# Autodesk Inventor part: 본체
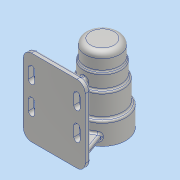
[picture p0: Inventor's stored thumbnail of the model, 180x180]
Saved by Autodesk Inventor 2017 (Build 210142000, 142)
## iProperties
Part Number: 본체
Material: 알루미늄 6061
Document SubType Name: Modeling
Designer: MRC
Density: 2.7 g/cm^3
Appearance: 알루미늄 - 평지
Mass: 691.206 g
Surface Area: 698.864 cm^2
Volume: 256.002 cm^3
Author: MRC
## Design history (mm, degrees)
sketch "스케치1"
  geometry: L1 (0, -56)-(34, -56); L2 (34, -56)-(34, -24); L3 (34, -24)-(30, -24); L4 (30, -24)-(30, 10); L5 (30, 10)-(27, 10); L6 (27, 10)-(27, 32); L7 (27, 32)-(25, 32); L8 (25, 32)-(25, 56); L9 (25, 56)-(0, 56); L10 (0, -56)-(0, 56); L11 (21, -56)-(21, -41); L12 (21, -41)-(24, -41); L13 (24, -41)-(24, 13); L14 (24, 13)-(21, 13); L15 (21, 13)-(21, 25); L16 (21, 25)-(17.5, 25); L17 (17.5, 25)-(17.5, 43); L18 (17.5, 43)-(16, 43); L19 (16, 43)-(16, 47); L20 (16, 47)-(10.5, 47); L21 (10.5, 47)-(10.5, 50); L22 (10.5, 50)-(0, 50); L23 (-62, 56)-(-70, 56); L24 (-70, 56)-(-70, -56); L25 (-70, -56)-(-62, -56); L26 (-62, -56)-(-62, 56); 4 further points
  constraints: 52 end point, 13 perpendicular, 8 horizontal, 3 midpoint, 3 parallel, 2 horizontal alignment, 2 point on line, 2 vertical, 1 coincident, 1 vertical alignment
  dimensions: "d0" = 112 distance between parallel lines of L1 L9; "d5" = 24 distance from line of L6.end L9; "d6" = 46 distance between parallel lines of L5 L9; "d7" = 80 distance between parallel lines of L3 L9; "d8" = 68 diameter of L2 L10; "d9" = 60 diameter of L4 L10; "d10" = 54 diameter of L6 L10; "d11" = 50 diameter of L8 L10; "d12" = 42 diameter of L11 L10; "d13" = 15 distance of L11.start L11.end; "d14" = 48 diameter of L13 L10; "d15" = 54 distance of L12.end L13.end; "d16" = 12 distance of L14.end L15.end; "d17" = 18 distance of L16.end L17.end; "d18" = 35 diameter of L17 L10; "d19" = 32 diameter of L19 L10; "d20" = 21 diameter of L21 L10; "d21" = 4 distance between parallel lines of L18 L20; "d22" = 3 distance between parallel lines of L20 L22; "d23" = 70 distance between parallel lines of L24 L10; "d24" = 8 distance of L24.end L25.end
revolve "회전1" stored, may be unused: angle "d25" = 90 deg
extrude "돌출1" join sketch "스케치1" stored distance "d26" = 90; taper "d27" = 0 deg
sketch "스케치2"
  geometry: L1 (-25, 56)-(25, 56) reference; L2 (25, 56)-(25, 32) reference; L3 (25, 32)-(27, 32) reference; L4 (27, 32)-(27, 10) reference; L5 (27, 10)-(30, 10) reference; L6 (30, 10)-(30, -24) reference; L7 (30, -24)-(34, -24) reference; L8 (34, -24)-(34, -56) reference; L9 (34, -56)-(21, -56) reference; L10 (21, -56)-(21, -41) reference; L11 (21, -41)-(24, -41) reference; L12 (24, -41)-(24, 13) reference; L13 (24, 13)-(21, 13) reference; L14 (21, 13)-(21, 25) reference; L15 (21, 25)-(17.5, 25) reference; L16 (17.5, 25)-(17.5, 43) reference; L17 (17.5, 43)-(16, 43) reference; L18 (16, 43)-(16, 47) reference; L19 (16, 47)-(10.5, 47) reference; L20 (10.5, 47)-(10.5, 50) reference; L21 (10.5, 50)-(-10.5, 50) reference; L22 (-10.5, 50)-(-10.5, 47) reference; L23 (-10.5, 47)-(-16, 47) reference; L24 (-16, 47)-(-16, 43) reference; L25 (-16, 43)-(-17.5, 43) reference; L26 (-17.5, 43)-(-17.5, 25) reference; L27 (-17.5, 25)-(-21, 25) reference; L28 (-21, 25)-(-21, 13) reference; L29 (-21, 13)-(-24, 13) reference; L30 (-24, 13)-(-24, -41) reference; L31 (-24, -41)-(-21, -41) reference; L32 (-21, -41)-(-21, -56) reference; L33 (-21, -56)-(-34, -56) reference; L34 (-34, -56)-(-34, -24) reference; L35 (-34, -24)-(-30, -24) reference; L36 (-30, -24)-(-30, 10) reference; L37 (-30, 10)-(-27, 10) reference; L38 (-27, 10)-(-27, 32) reference; L39 (-27, 32)-(-25, 32) reference; L40 (-25, 32)-(-25, 56) reference; L41 (-62, 56)-(-62, -56) reference; L42 (-62, -56)-(-70, -56) reference; L43 (-70, -56)-(-70, 56) reference; L44 (-70, 56)-(-62, 56) reference; L45 (-62, 29)-(-26.114, 19.384); 1 further point
  constraints: 2 end point, 1 point on line
  dimensions: "d28" = 105 deg angle of L45 L41; "d29" = 85 distance from line of L42 L45.start
  node "절단 모서리 투영1"
node "작업 평면1"
sketch "스케치3"
  geometry: L1 (45, -62)-(45, -70) reference; L2 (45, -70)-(-45, -70) reference; L3 (-45, -70)-(-45, -62) reference; L4 (-45, -62)-(45, -62) reference; L5 (-45, -62)-(45, -62) reference; L6 (-37, -62)-(-23.409, -24.658); C1 r 21 at (0, 0) reference; 3 further points
  constraints: 2 end point, 1 point on line, 4 other
  dimensions: "d31" = 8 distance from line of L6.start L3; "d32" = 110 deg angle of L6 L4
feature "리브1" sketch "스케치3" dims "d33" = 40, "d34" = 8, "d35" = 0, "d36" = 0, "d37" = 1, "d38" = 1
feature "리브2" dims "d39" = 40, "d40" = 8, "d41" = 0, "d42" = 0, "d43" = 1, "d44" = 1
sketch "스케치4"
  geometry: L1 (0, 112)-(90, 112) reference; L2 (12, 92)-(12, 77); L3 (7.5, 92)-(7.5, 77); L4 (16.5, 77)-(16.5, 92); L5 (0, 0)-(0, 112) reference; L6 (0, 112)-(90, 112) reference; L7 (90, 112)-(90, 0) reference; L8 (90, 0)-(0, 0) reference; L9 (12, 52)-(12, 37); L10 (7.5, 52)-(7.5, 37); L11 (16.5, 37)-(16.5, 52); L12 (78, 92)-(78, 77); L13 (73.5, 92)-(73.5, 77); L14 (82.5, 77)-(82.5, 92); L15 (78, 52)-(78, 37); L16 (73.5, 52)-(73.5, 37); L17 (82.5, 37)-(82.5, 52); A1 r 4.5 centre (12, 92) between (16.5, 92) and (7.5, 92); A2 r 4.5 centre (12, 77) between (7.5, 77) and (16.5, 77); A3 r 4.5 centre (12, 52) between (16.5, 52) and (7.5, 52); A4 r 4.5 centre (12, 37) between (7.5, 37) and (16.5, 37); A5 r 4.5 centre (78, 92) between (82.5, 92) and (73.5, 92); A6 r 4.5 centre (78, 77) between (73.5, 77) and (82.5, 77); A7 r 4.5 centre (78, 52) between (82.5, 52) and (73.5, 52); A8 r 4.5 centre (78, 37) between (73.5, 37) and (82.5, 37); 5 further points
  constraints: 32 end point, 16 point on circle, 16 tangent, 8 centre point, 5 parallel, 4 midpoint, 3 equal length, 3 equal radius, 3 vertical, 2 vertical alignment, 1 horizontal alignment
  dimensions: "d45" = 15 distance of L2.start L2.end; "d46" = 9 distance between parallel lines of L3 L4; "d47" = 20 distance from line of L2.start L1; "d48" = 33 horizontal distance of point (45, 56) point (12, 84.5); "d49" = 25 distance of L9.start L2.end; "d50" = 33 horizontal distance of point (45, 56) L12.start; "d51" = 20 distance from line of L12.start L1
extrude "돌출2" cut sketch "스케치4" distance "d52" = 20; taper "d53" = 0 deg
fillet "모깎기1" dims "d54" = 12
fillet "모깎기2" dims "d55" = 0.3
sketch "스케치5"
  geometry: L1 (0, 0)-(22.84, 39.56); L2 (0, 0)-(-47.681, 0); C1 r 21 at (0, 0) reference; C2 r 34 at (0, 0) reference; 1 further point
  constraints: 4 end point, 1 horizontal, 1 point on line
  dimensions: "d56" = 120 deg angle of L2 L1; "d57" = 26 distance of C1.centre point (13, 22.517)
hole "구멍1" sketch "스케치5" at (13, 22.517) diameter "d58" = 3.242; stored, may be unused: countersink angle "d62" = 90 deg, drill point angle "d64" = 118 deg; dims "d59" = 8, "d60" = 4, "d61" = 2, "d63" = 11
chamfer "모따기2" distance "d73" = 1; stored, may be unused: second distance "d74" = 2, angle "d75" = 45 deg
fillet "모깎기5" dims "d76" = 3
fillet "모깎기6" dims "d77" = 3
fillet "모깎기7" dims "d78" = 3
sketch "스케치6"
  geometry: L1 (0, -109)-(66, -109) reference; 3 further points
  constraints: 1 midpoint, 1 vertical alignment, 1 other
  dimensions: "d79" = 12 distance from line of point (33, -97) L1
feature "엠보싱1" sketch "스케치6" dims "d0" = 112, "d5" = 24, "d6" = 46, "d7" = 80, "d8" = 68, "d9" = 60, "d10" = 54, "d11" = 50, "d12" = 42, "d13" = 15, "d14" = 48, "d15" = 54, "d16" = 12, "d17" = 18, "d18" = 35, "d19" = 32, "d20" = 21, "d21" = 4, "d22" = 3, "d23" = 70, "d24" = 8, "d80" = 0.5, "d81" = 0
fillet "모깎기8" dims "d82" = 8
node "솔리드1"
mirror "미러1"
pattern_circular "원형 패턴1" dims angle "d66" = 360 deg
node "절단 모서리 투영2"
node "절단 모서리 투영3"
other parameters: "d30" = -8
